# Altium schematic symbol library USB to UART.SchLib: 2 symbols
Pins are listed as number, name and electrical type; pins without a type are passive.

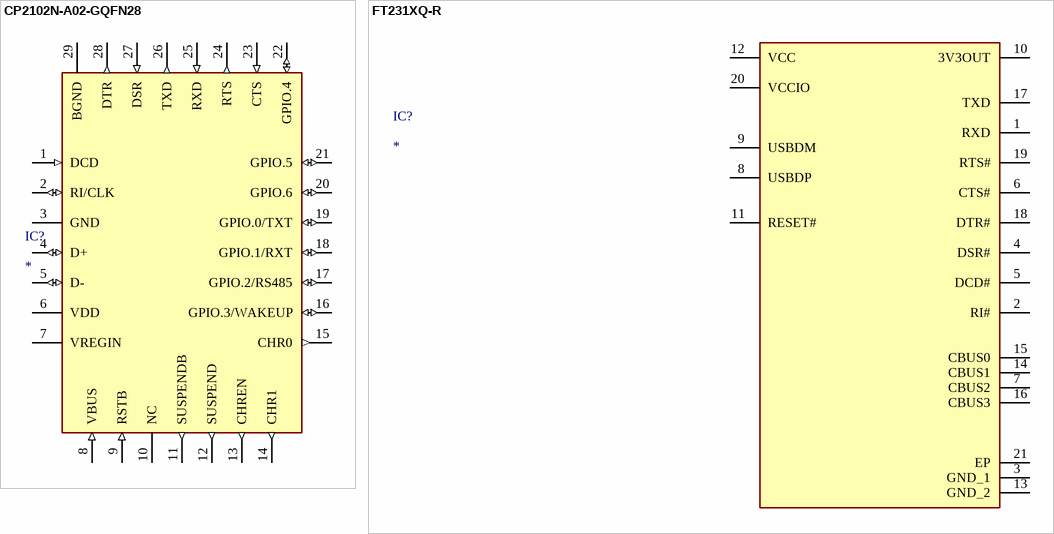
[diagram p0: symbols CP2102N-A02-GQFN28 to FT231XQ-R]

## CP2102N-A02-GQFN28
designator IC?
Integrated Circuit; Manufacturer_Name: Silicon Labs; Manufacturer_Part_Number: CP2102N-A02-GQFN28; Description: SILICON LABS - CP2102N-A02-GQFN28 - USB TO UART BRIDGE
footprint QFN50P500X500X80-29N-D
pins: 1 DCD (in), 2 RI/CLK (io), 3 GND (power), 4 D+ (io), 5 D- (io), 6 VDD (power), 7 VREGIN (power), 8 VBUS (in), 9 RSTB (in), 10 NC, 11 SUSPENDB (out), 12 SUSPEND (out), 13 CHREN (out), 14 CHR1 (out), 15 CHR0 (out), 16 GPIO.3/WAKEUP (io), 17 GPIO.2/RS485 (io), 18 GPIO.1/RXT (io), 19 GPIO.0/TXT (io), 20 GPIO.6 (io), 21 GPIO.5 (io), 22 GPIO.4 (io), 23 CTS (in), 24 RTS (out), 25 RXD (in), 26 TXD (out), 27 DSR (in), 28 DTR (out), 29 BGND (power)

## FT231XQ-R
designator IC?
Integrated Circuit; Manufacturer_Name: FTDI Chip; Manufacturer_Part_Number: FT231XQ-R
footprint QFN50P400X400X80-21N
pins: 1 RXD, 2 RI#, 3 GND_1, 4 DSR#, 5 DCD#, 6 CTS#, 7 CBUS2, 8 USBDP, 9 USBDM, 10 3V3OUT, 11 RESET#, 12 VCC, 13 GND_2, 14 CBUS1, 15 CBUS0, 16 CBUS3, 17 TXD, 18 DTR#, 19 RTS#, 20 VCCIO, 21 EP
